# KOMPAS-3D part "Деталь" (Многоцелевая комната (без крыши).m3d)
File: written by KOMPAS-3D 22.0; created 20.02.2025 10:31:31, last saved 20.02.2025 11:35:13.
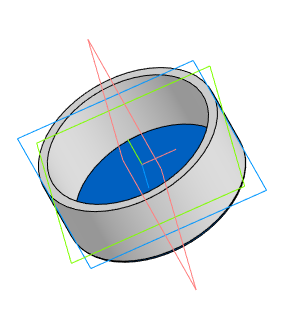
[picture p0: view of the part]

Document properties: Автор: Пользователь Windows; Полное имя файла: C:\Users\Student\Documents\Картошечка\База Сабнатика\Многоцелевая комната\Многоцелевая комната (без крыши).m3d

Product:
- Part/product: Деталь
    Масса: 0.11405

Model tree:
1. Эскиз:3
2. Элемент вращения:1
     Угол 1 = 360
3. Скругление:1  (with: Элемент вращения:1)
     Радиус = 1
4. Эскиз:4  (with: Элемент вращения:1)
5. Элемент выдавливания:1
     Расстояние 2 = 6.1
6. Эскиз:5  (with: Элемент выдавливания:1)
7. Элемент выдавливания:2
     Расстояние 2 = 19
